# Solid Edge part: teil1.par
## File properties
Author: Susi
Template: normal.par
Last saved by: Susi
Revision: 2
Application: Solid Edge
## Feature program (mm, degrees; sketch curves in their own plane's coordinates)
sketch for "unnamed Protrusion 1" plane through (0, 0, 0) normal (0, 0, 1) x-axis (1, 0, 0)
extrude "unnamed Protrusion 1" add finite 10 along +normal
sketch for "unnamed Cutout 1" #1 plane through (33.7333, 33.4667, 10) normal (0, 0, 1) x-axis (0, 1, 0)
  circle centre (-10, -25) radius 10
sketch for "unnamed Cutout 1" #2 plane through (33.7333, 33.4667, 10) normal (0, 0, 1) x-axis (0, 1, 0)
  circle centre (-10, 25) radius 10
sketch for "unnamed Cutout 1" #3 plane through (33.7333, 33.4667, 10) normal (0, 0, 1) x-axis (0, 1, 0)
  circle centre (-10, 0) radius 10
sketch for "unnamed Cutout 1" #4 plane through (33.7333, 33.4667, 10) normal (0, 0, 1) x-axis (0, 1, 0)
extrude "unnamed Cutout 1" cut finite 10 along -normal
sketch for "unnamed Cutout 2" #1 plane through (33.7333, 33.4667, 10) normal (0, 0, 1) x-axis (0, 1, 0)
  circle centre (-10, 25) radius 10
sketch for "unnamed Cutout 2" #2 plane through (33.7333, 33.4667, 10) normal (0, 0, 1) x-axis (0, 1, 0)
  circle centre (-10, 0) radius 10
sketch for "unnamed Cutout 2" #3 plane through (33.7333, 33.4667, 10) normal (0, 0, 1) x-axis (0, 1, 0)
  circle centre (-10, -25) radius 10
extrude "unnamed Cutout 2" cut finite 38.1 along -normal
sketch for "unnamed Cutout 3" #1 plane through (33.7333, 33.4667, 10) normal (0, 0, 1) x-axis (0, 1, 0)
  line (27.4444, 0) -> (27.4444, 5)
  line (27.4444, 5) -> (32.4444, 5)
  line (32.4444, 5) -> (32.4444, 0)
  line (32.4444, 0) -> (27.4444, 0)
sketch for "unnamed Cutout 3" #2 plane through (33.7333, 33.4667, 10) normal (0, 0, 1) x-axis (0, 1, 0)
  line (25, -25) -> (25, -40)
  line (25, -40) -> (27, -40)
  line (27, -40) -> (27, -25)
  line (27, -25) -> (25, -25)
sketch for "unnamed Cutout 3" #3 plane through (33.7333, 33.4667, 10) normal (0, 0, 1) x-axis (0, 1, 0)
  line (35, -25) -> (35, -40)
  line (35, -40) -> (33, -40)
  line (33, -40) -> (33, -25)
  line (33, -25) -> (35, -25)
sketch for "unnamed Cutout 3" #4 plane through (33.7333, 33.4667, 10) normal (0, 0, 1) x-axis (0, 1, 0)
  line (35, 0) -> (25, 0)
  line (25, 0) -> (25, -25)
  line (25, -25) -> (35, -25)
  line (35, -25) -> (35, 0)
extrude "unnamed Cutout 3" cut finite 28.575 along -normal
sketch for "unnamed Cutout 4" plane through (33.7333, 33.4667, 10) normal (0, 0, 1) x-axis (0, 1, 0)
  circle centre (29.9444, 5) radius 4
extrude "unnamed Cutout 4" cut finite 22.225 along -normal
sketch for "unnamed Cutout 5" plane through (33.7333, 33.4667, 10) normal (0, 0, 1) x-axis (0, 1, 0)
  circle centre (35, 35) radius 10
extrude "unnamed Cutout 5" cut finite 44.45 along -normal
sketch for "unnamed Protrusion 2" plane through (33.7333, 33.4667, 10) normal (0, 0, 1) x-axis (0, 1, 0)
  line (27.4444, 0) -> (27.4444, 5)
  line (27.4444, 5) -> (32.4444, 5)
  line (32.4444, 5) -> (32.4444, 0)
  line (32.4444, 0) -> (27.4444, 0)
extrude "unnamed Protrusion 2" add finite 22.225 along -normal
sketch for "unnamed Cutout 6" plane through (33.7333, 33.4667, 10) normal (0, 0, 1) x-axis (0, 1, 0)
  line (32.4444, 0) -> (32.4444, 5)
  line (32.4444, 5) -> (27.4444, 5)
  line (27.4444, 5) -> (27.4444, 0)
  line (27.4444, 0) -> (32.4444, 0)
extrude "unnamed Cutout 6" cut finite 41.275 along -normal
sketch for "unnamed Protrusion 3" plane through (33.7333, 33.4667, 10) normal (0, 0, 1) x-axis (0, 1, 0)
  circle centre (29.9444, 5) radius 4
extrude "unnamed Protrusion 3" add finite 19.05 along -normal
sketch for "unnamed Protrusion 4" plane through (33.7333, 33.4667, 10) normal (0, 0, 1) x-axis (0, 1, 0)
  line (27.4444, 0) -> (32.4444, 0)
  line (32.4444, 0) -> (32.4444, 1.8775)
  line (32.4444, 1.8775) -> (27.4444, 1.8775)
  line (27.4444, 1.8775) -> (27.4444, 0)
extrude "unnamed Protrusion 4" add finite 41.275 along -normal
sketch for "unnamed Cutout 7" plane through (33.7333, 33.4667, 0) normal (0, 0, -1) x-axis (0, 1, 0)
  circle centre (29.9444, -5) radius 4
extrude "unnamed Cutout 7" cut finite 44.45 along +normal
sketch for "unnamed Cutout 8" plane through (33.7333, 33.4667, 0) normal (0, 0, -1) x-axis (0, 1, 0)
  line (32.4444, 0) -> (32.4444, -1.8775)
  line (32.4444, -1.8775) -> (27.7778, -1.8775)
  line (27.7778, -1.8775) -> (27.7778, 0)
  line (27.7778, 0) -> (32.4444, 0)
extrude "unnamed Cutout 8" cut finite 76.2 along +normal
sketch for "unnamed Cutout 9" plane through (32.7946, 60.9111, -15.6375) normal (0, -1, 0) x-axis (0, 0, -1)
  line (-15.6375, 0.9388) -> (-15.6375, -0.9388)
  line (-15.6375, -0.9388) -> (15.6375, -0.9388)
  line (15.6375, -0.9388) -> (15.6375, 0.9388)
  line (15.6375, 0.9388) -> (-15.6375, 0.9388)
extrude "unnamed Cutout 9" cut finite 57.15 symmetric
sketch for "unnamed Cutout 10" plane through (33.7333, 33.4667, 10) normal (0, 0, 1) x-axis (0, 1, 0)
  circle centre (30, 5) radius 4
extrude "unnamed Cutout 10" cut finite 53.975 along -normal
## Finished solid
Body 1: solid body, 20 faces, 52 edges, 32 vertices.
  Faces by surface: plane 18, cylinder 2
  Edges by curve: line 48, circle 4
Bounding box of the edges (mm): 100.000 x 100.000 x 10.000, from (-16.2667, -16.5333, 0) to (83.7333, 83.4667, 10).
Cylindrical faces by radius (mm): R4 x1, R10 x1
Planar faces by outward normal: +x 3, +y 4, +z 1, -x 5, -y 4, -z 1
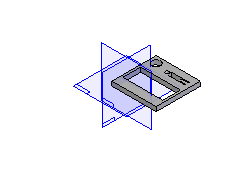
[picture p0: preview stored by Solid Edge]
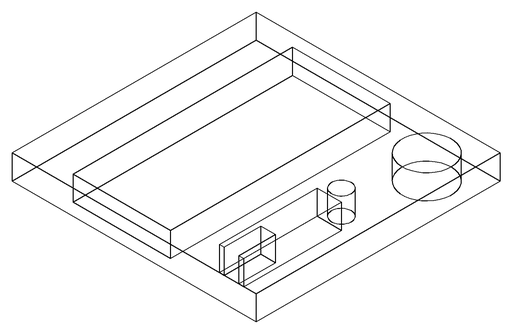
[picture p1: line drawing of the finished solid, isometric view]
